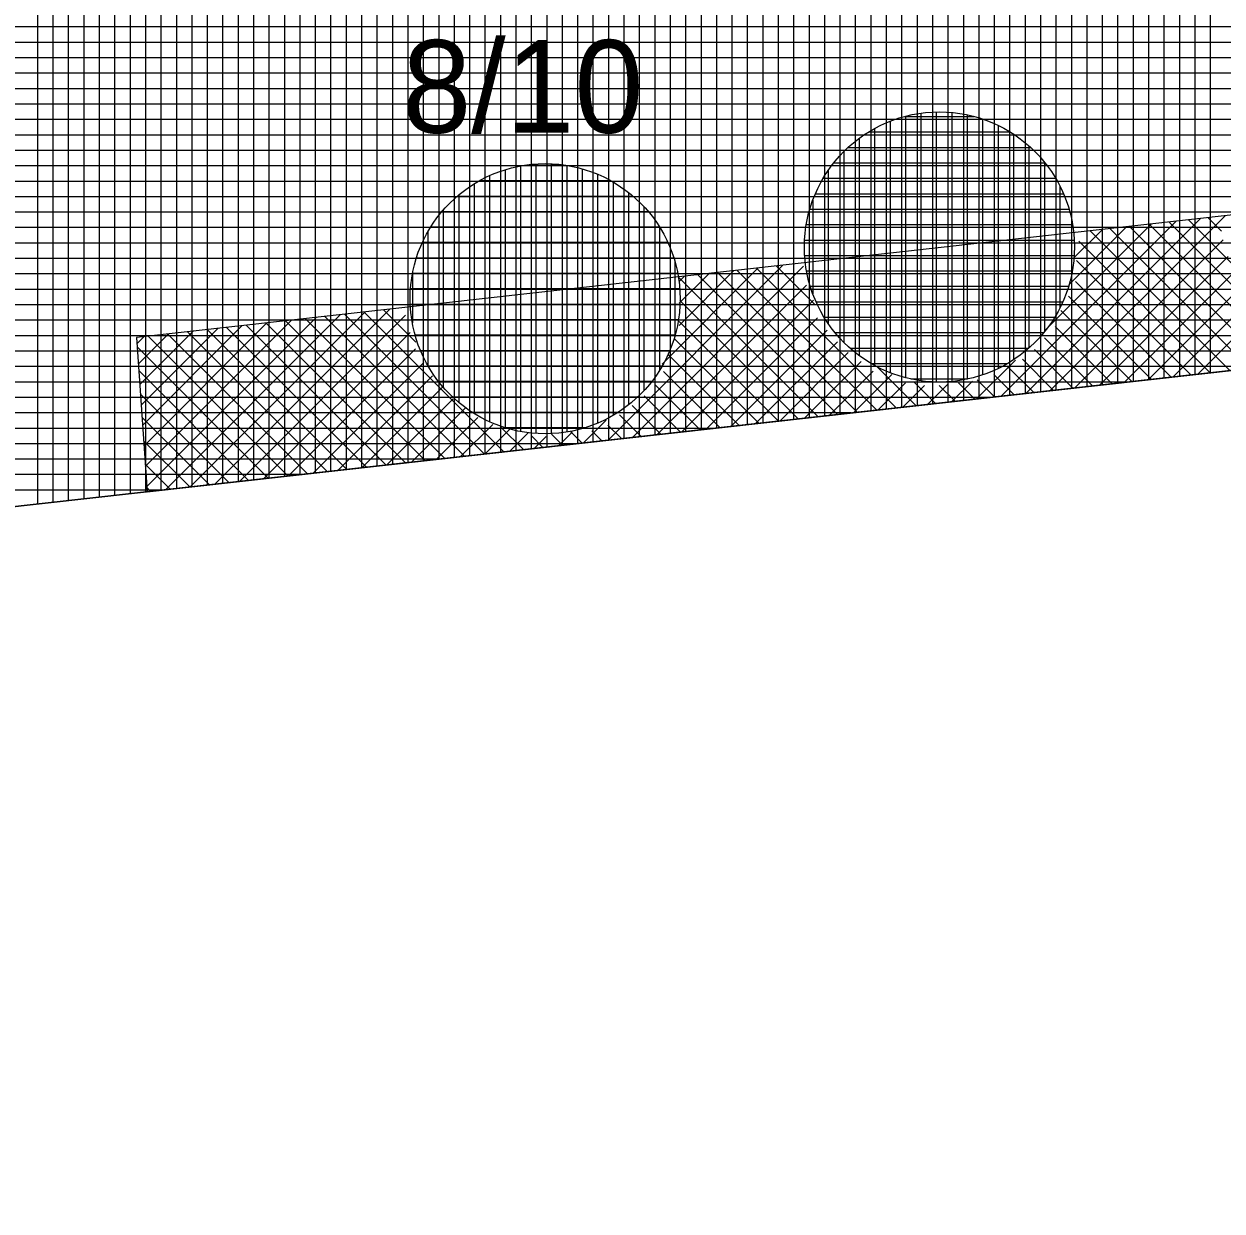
# Model space of a CAD drawing. Extents: x -565346 to -564154, y -1097386 to -1095620.
# Drawn here: x -565167.9 to -565152.37, y -1095873.28 to -1095857.9 of the extents above; entities that cross this region are included whole.
import ezdxf

# ---------------------------------------------------------------- set-up
doc = ezdxf.new("R2010")
doc.units = 0
for name, color, linetype in [('Vrstva 1', 7, 'Continuous'), ('Vrstva 40', 7, 'Continuous'), ('Vrstva 41', 7, 'Continuous'), ('Vrstva 42', 7, 'Continuous'), ('Vrstva 43', 7, 'Continuous'), ('Vrstva 44', 7, 'Continuous')]:
    doc.layers.add(name, color=color, linetype=linetype)

msp = doc.modelspace()

# ---------------------------------------------------------------- linework, layer by layer
at = {"layer": 'Vrstva 1'}
msp.add_line((-565052.84, -1095851.27), (-565230.93, -1095871.19), dxfattribs=at)
at = {"layer": 'Vrstva 41'}
for p, q in [((-565152.963, -1095860.456), (-565155.23, -1095862.723)), ((-565152.645, -1095860.42), (-565154.911, -1095862.687)), ((-565152.326, -1095860.385), (-565154.593, -1095862.651)), ((-565152.201, -1095861.041), (-565152.803, -1095860.438)), ((-565152.374, -1095860.584), (-565152.549, -1095860.41)), ((-565153.281, -1095860.492), (-565154.655, -1095861.865)), ((-565153.6, -1095860.527), (-565154.351, -1095861.279)), ((-565153.918, -1095860.563), (-565154.293, -1095860.937)), ((-565152.264, -1095862.391), (-565154.075, -1095860.58)), ((-565152.01, -1095862.363), (-565153.821, -1095860.552)), ((-565151.756, -1095862.334), (-565153.566, -1095860.523)), ((-565151.501, -1095862.306), (-565153.312, -1095860.495)), ((-565151.247, -1095862.277), (-565153.057, -1095860.466)), ((-565152.354, -1095860.696), (-565154.274, -1095862.616)), ((-565152.519, -1095862.419), (-565154.224, -1095860.714)), ((-565152.288, -1095860.912), (-565153.956, -1095862.58)), ((-565158.058, -1095861.026), (-565160.325, -1095863.293)), ((-565157.79, -1095861.04), (-565160.007, -1095863.257)), ((-565158.377, -1095861.061), (-565159.623, -1095862.307)), ((-565156.589, -1095862.875), (-565158.4, -1095861.064)), ((-565157.645, -1095861.535), (-565158.145, -1095861.036)), ((-565152.773, -1095862.448), (-565154.255, -1095860.965)), ((-565157.606, -1095862.988), (-565159.417, -1095861.178)), ((-565158.695, -1095861.097), (-565159.404, -1095861.806)), ((-565159.014, -1095861.133), (-565159.401, -1095861.519)), ((-565159.332, -1095861.168), (-565159.397, -1095861.233)), ((-565157.352, -1095862.96), (-565159.163, -1095861.149)), ((-565157.098, -1095862.932), (-565158.908, -1095861.121)), ((-565156.843, -1095862.903), (-565158.654, -1095861.092)), ((-565152.196, -1095861.104), (-565153.637, -1095862.545)), ((-565157.753, -1095861.287), (-565159.688, -1095863.221)), ((-565153.027, -1095862.476), (-565154.267, -1095861.237)), ((-565152.105, -1095861.295), (-565153.319, -1095862.509)), ((-565157.861, -1095863.017), (-565159.394, -1095861.484)), ((-565157.662, -1095861.478), (-565159.37, -1095863.186)), ((-565153.282, -1095862.505), (-565154.358, -1095861.428)), ((-565151.954, -1095861.426), (-565153.001, -1095862.473)), ((-565163.791, -1095861.667), (-565166.058, -1095863.934)), ((-565163.472, -1095861.631), (-565165.739, -1095863.898)), ((-565163.154, -1095861.596), (-565165.421, -1095863.863)), ((-565162.948, -1095861.672), (-565165.102, -1095863.827)), ((-565162.185, -1095863.501), (-565163.996, -1095861.69)), ((-565161.931, -1095863.472), (-565163.742, -1095861.662)), ((-565161.677, -1095863.444), (-565163.487, -1095861.633)), ((-565162.814, -1095862.024), (-565163.233, -1095861.605)), ((-565153.536, -1095862.533), (-565154.455, -1095861.615)), ((-565151.817, -1095861.573), (-565152.682, -1095862.438)), ((-565165.383, -1095861.845), (-565166.377, -1095862.839)), ((-565165.065, -1095861.809), (-565166.359, -1095863.104)), ((-565164.746, -1095861.774), (-565166.341, -1095863.369)), ((-565164.428, -1095861.738), (-565166.323, -1095863.633)), ((-565164.109, -1095861.703), (-565166.305, -1095863.898)), ((-565163.457, -1095863.643), (-565165.268, -1095861.832)), ((-565163.203, -1095863.614), (-565165.014, -1095861.804)), ((-565162.949, -1095863.586), (-565164.759, -1095861.775)), ((-565162.694, -1095863.558), (-565164.505, -1095861.747)), ((-565162.44, -1095863.529), (-565164.251, -1095861.718)), ((-565158.115, -1095863.045), (-565159.405, -1095861.755)), ((-565157.611, -1095861.709), (-565159.051, -1095863.15)), ((-565153.791, -1095862.562), (-565154.531, -1095861.821)), ((-565166.338, -1095861.952), (-565166.431, -1095862.045)), ((-565166.02, -1095861.916), (-565166.413, -1095862.31)), ((-565165.702, -1095861.881), (-565166.395, -1095862.574)), ((-565164.475, -1095863.757), (-565166.286, -1095861.946)), ((-565164.221, -1095863.728), (-565166.031, -1095861.918)), ((-565163.966, -1095863.7), (-565165.777, -1095861.889)), ((-565163.712, -1095863.671), (-565165.522, -1095861.861)), ((-565162.891, -1095861.899), (-565164.784, -1095863.791)), ((-565158.37, -1095863.074), (-565159.462, -1095861.982)), ((-565157.484, -1095861.866), (-565158.733, -1095863.114)), ((-565154.045, -1095862.59), (-565154.668, -1095861.968)), ((-565164.729, -1095863.785), (-565166.429, -1095862.086)), ((-565162.82, -1095862.11), (-565164.465, -1095863.756)), ((-565157.353, -1095862.017), (-565158.414, -1095863.079)), ((-565157.211, -1095862.159), (-565158.096, -1095863.043)), ((-565154.299, -1095862.619), (-565154.799, -1095862.119)), ((-565162.713, -1095862.287), (-565164.147, -1095863.72)), ((-565158.624, -1095863.102), (-565159.548, -1095862.178)), ((-565157.045, -1095862.275), (-565157.777, -1095863.008)), ((-565155.045, -1095862.255), (-565155.548, -1095862.758)), ((-565154.554, -1095862.647), (-565154.955, -1095862.245)), ((-565164.984, -1095863.814), (-565166.408, -1095862.39)), ((-565162.602, -1095862.458), (-565163.828, -1095863.684)), ((-565158.878, -1095863.131), (-565159.605, -1095862.405)), ((-565156.889, -1095862.401), (-565157.459, -1095862.972)), ((-565156.647, -1095862.443), (-565157.141, -1095862.936)), ((-565156.334, -1095862.846), (-565156.845, -1095862.335)), ((-565155.063, -1095862.704), (-565155.323, -1095862.443)), ((-565154.808, -1095862.676), (-565155.147, -1095862.337)), ((-565162.466, -1095862.604), (-565163.51, -1095863.649)), ((-565159.133, -1095863.159), (-565159.711, -1095862.581)), ((-565156.471, -1095862.549), (-565156.822, -1095862.901)), ((-565156.224, -1095862.586), (-565156.504, -1095862.865)), ((-565156.08, -1095862.818), (-565156.354, -1095862.544)), ((-565155.923, -1095862.567), (-565156.185, -1095862.83)), ((-565155.826, -1095862.789), (-565156.033, -1095862.583)), ((-565155.601, -1095862.529), (-565155.867, -1095862.794)), ((-565155.571, -1095862.761), (-565155.781, -1095862.551)), ((-565155.317, -1095862.732), (-565155.54, -1095862.51)), ((-565165.238, -1095863.842), (-565166.387, -1095862.693)), ((-565162.334, -1095862.756), (-565163.191, -1095863.613)), ((-565159.387, -1095863.188), (-565159.857, -1095862.717)), ((-565162.168, -1095862.872), (-565162.873, -1095863.578)), ((-565159.642, -1095863.216), (-565160.014, -1095862.844)), ((-565165.492, -1095863.871), (-565166.366, -1095862.997)), ((-565162.011, -1095862.999), (-565162.554, -1095863.542)), ((-565161.82, -1095863.09), (-565162.236, -1095863.506)), ((-565160.348, -1095863.032), (-565160.644, -1095863.328)), ((-565160.15, -1095863.273), (-565160.327, -1095863.097)), ((-565159.896, -1095863.245), (-565160.175, -1095862.965)), ((-565161.593, -1095863.147), (-565161.918, -1095863.471)), ((-565161.422, -1095863.415), (-565161.709, -1095863.129)), ((-565161.362, -1095863.198), (-565161.599, -1095863.435)), ((-565161.168, -1095863.387), (-565161.322, -1095863.232)), ((-565161.126, -1095863.244), (-565161.281, -1095863.399)), ((-565160.913, -1095863.358), (-565161.056, -1095863.216)), ((-565160.789, -1095863.191), (-565160.962, -1095863.364)), ((-565160.659, -1095863.33), (-565160.805, -1095863.185)), ((-565160.405, -1095863.301), (-565160.533, -1095863.173)), ((-565165.747, -1095863.899), (-565166.346, -1095863.3)), ((-565166.001, -1095863.927), (-565166.325, -1095863.604)), ((-565166.256, -1095863.956), (-565166.304, -1095863.908))]:
    msp.add_line(p, q, dxfattribs=at)
at = {"layer": 'Vrstva 42'}
msp.add_lwpolyline([(-565166.437, -1095861.963), (-565166.3, -1095863.961), (-565065.713, -1095852.71), (-565065.975, -1095850.726)], close=True, dxfattribs=at)
at = {"layer": 'Vrstva 43'}
for p, q in [((-565154.72, -1095848.037), (-565154.72, -1095862.666)), ((-565154.52, -1095848.023), (-565154.52, -1095862.643)), ((-565154.32, -1095848.009), (-565154.32, -1095862.621)), ((-565154.12, -1095847.996), (-565154.12, -1095862.599)), ((-565153.92, -1095847.982), (-565153.92, -1095862.576)), ((-565153.72, -1095847.968), (-565153.72, -1095862.554)), ((-565153.52, -1095847.954), (-565153.52, -1095862.531)), ((-565153.32, -1095847.941), (-565153.32, -1095862.509)), ((-565153.12, -1095847.927), (-565153.12, -1095862.487)), ((-565152.92, -1095847.913), (-565152.92, -1095862.464)), ((-565152.72, -1095847.9), (-565152.72, -1095862.442)), ((-565152.52, -1095847.886), (-565152.52, -1095862.42)), ((-565156.92, -1095848.188), (-565156.92, -1095862.912)), ((-565156.72, -1095848.174), (-565156.72, -1095862.889)), ((-565156.52, -1095848.16), (-565156.52, -1095862.867)), ((-565156.32, -1095848.146), (-565156.32, -1095862.845)), ((-565156.12, -1095848.133), (-565156.12, -1095862.822)), ((-565155.92, -1095848.119), (-565155.92, -1095862.8)), ((-565155.72, -1095848.105), (-565155.72, -1095862.777)), ((-565155.52, -1095848.092), (-565155.52, -1095862.755)), ((-565155.32, -1095848.078), (-565155.32, -1095862.733)), ((-565155.12, -1095848.064), (-565155.12, -1095862.71)), ((-565154.92, -1095848.05), (-565154.92, -1095862.688)), ((-565159.12, -1095848.339), (-565159.12, -1095863.158)), ((-565158.92, -1095848.325), (-565158.92, -1095863.135)), ((-565158.72, -1095848.311), (-565158.72, -1095863.113)), ((-565158.52, -1095848.297), (-565158.52, -1095863.091)), ((-565158.32, -1095848.284), (-565158.32, -1095863.068)), ((-565158.12, -1095848.27), (-565158.12, -1095863.046)), ((-565157.92, -1095848.256), (-565157.92, -1095863.024)), ((-565157.72, -1095848.243), (-565157.72, -1095863.001)), ((-565157.52, -1095848.229), (-565157.52, -1095862.979)), ((-565157.32, -1095848.215), (-565157.32, -1095862.956)), ((-565157.12, -1095848.201), (-565157.12, -1095862.934)), ((-565161.32, -1095848.489), (-565161.32, -1095863.404)), ((-565161.12, -1095848.476), (-565161.12, -1095863.382)), ((-565160.92, -1095848.462), (-565160.92, -1095863.359)), ((-565160.72, -1095848.448), (-565160.72, -1095863.337)), ((-565160.52, -1095848.435), (-565160.52, -1095863.314)), ((-565160.32, -1095848.421), (-565160.32, -1095863.292)), ((-565160.12, -1095848.407), (-565160.12, -1095863.27)), ((-565159.92, -1095848.393), (-565159.92, -1095863.247)), ((-565159.72, -1095848.38), (-565159.72, -1095863.225)), ((-565159.52, -1095848.366), (-565159.52, -1095863.203)), ((-565159.32, -1095848.352), (-565159.32, -1095863.18)), ((-565163.72, -1095848.654), (-565163.72, -1095863.672)), ((-565163.52, -1095848.64), (-565163.52, -1095863.65)), ((-565163.32, -1095848.627), (-565163.32, -1095863.628)), ((-565163.12, -1095848.613), (-565163.12, -1095863.605)), ((-565162.92, -1095848.599), (-565162.92, -1095863.583)), ((-565162.72, -1095848.585), (-565162.72, -1095863.56)), ((-565162.52, -1095848.572), (-565162.52, -1095863.538)), ((-565162.32, -1095848.558), (-565162.32, -1095863.516)), ((-565162.12, -1095848.544), (-565162.12, -1095863.493)), ((-565161.92, -1095848.531), (-565161.92, -1095863.471)), ((-565161.72, -1095848.517), (-565161.72, -1095863.449)), ((-565161.52, -1095848.503), (-565161.52, -1095863.426)), ((-565165.92, -1095848.805), (-565165.92, -1095863.918)), ((-565165.72, -1095848.791), (-565165.72, -1095863.896)), ((-565165.52, -1095848.778), (-565165.52, -1095863.874)), ((-565165.32, -1095848.764), (-565165.32, -1095863.851)), ((-565165.12, -1095848.75), (-565165.12, -1095863.829)), ((-565164.92, -1095848.736), (-565164.92, -1095863.807)), ((-565164.72, -1095848.723), (-565164.72, -1095863.784)), ((-565164.52, -1095848.709), (-565164.52, -1095863.762)), ((-565164.32, -1095848.695), (-565164.32, -1095863.739)), ((-565164.12, -1095848.681), (-565164.12, -1095863.717)), ((-565163.92, -1095848.668), (-565163.92, -1095863.695)), ((-565167.72, -1095848.928), (-565167.72, -1095864.12)), ((-565167.52, -1095848.915), (-565167.52, -1095864.097)), ((-565167.32, -1095848.901), (-565167.32, -1095864.075)), ((-565167.12, -1095848.887), (-565167.12, -1095864.053)), ((-565166.92, -1095848.874), (-565166.92, -1095864.03)), ((-565166.72, -1095848.86), (-565166.72, -1095864.008)), ((-565166.52, -1095848.846), (-565166.52, -1095863.986)), ((-565166.32, -1095848.832), (-565166.32, -1095863.963)), ((-565166.12, -1095848.819), (-565166.12, -1095863.941)), ((-565112.472, -1095857.94), (-565307.466, -1095857.94)), ((-565114.26, -1095858.14), (-565322.58, -1095858.14)), ((-565116.048, -1095858.34), (-565322.576, -1095858.34)), ((-565117.836, -1095858.54), (-565322.572, -1095858.54)), ((-565119.624, -1095858.74), (-565322.568, -1095858.74)), ((-565121.412, -1095858.94), (-565322.564, -1095858.94)), ((-565123.2, -1095859.14), (-565322.56, -1095859.14)), ((-565124.988, -1095859.34), (-565322.556, -1095859.34)), ((-565126.776, -1095859.54), (-565322.552, -1095859.54)), ((-565128.564, -1095859.74), (-565322.548, -1095859.74)), ((-565130.352, -1095859.94), (-565322.544, -1095859.94)), ((-565132.14, -1095860.14), (-565322.541, -1095860.14)), ((-565133.928, -1095860.34), (-565322.537, -1095860.34)), ((-565135.716, -1095860.54), (-565322.533, -1095860.54)), ((-565137.504, -1095860.74), (-565322.529, -1095860.74)), ((-565139.292, -1095860.94), (-565322.525, -1095860.94)), ((-565141.08, -1095861.14), (-565322.521, -1095861.14)), ((-565142.868, -1095861.34), (-565322.517, -1095861.34)), ((-565144.656, -1095861.54), (-565322.513, -1095861.54)), ((-565146.445, -1095861.74), (-565322.509, -1095861.74)), ((-565148.233, -1095861.94), (-565322.505, -1095861.94)), ((-565150.021, -1095862.14), (-565322.501, -1095862.14)), ((-565151.809, -1095862.34), (-565322.497, -1095862.34)), ((-565153.597, -1095862.54), (-565322.493, -1095862.54)), ((-565155.385, -1095862.74), (-565322.489, -1095862.74)), ((-565157.173, -1095862.94), (-565322.485, -1095862.94)), ((-565158.961, -1095863.14), (-565322.481, -1095863.14)), ((-565160.749, -1095863.34), (-565322.477, -1095863.34)), ((-565162.537, -1095863.54), (-565322.473, -1095863.54)), ((-565164.325, -1095863.74), (-565322.469, -1095863.74)), ((-565166.113, -1095863.94), (-565322.465, -1095863.94))]:
    msp.add_line(p, q, dxfattribs=at)
msp.add_lwpolyline([(-565311.82, -1095858.04), (-565322.62, -1095856.13), (-565322.28, -1095873.28), (-565318.28, -1095873.19), (-565230.93, -1095871.19), (-565052.84, -1095851.27), (-565052.77, -1095836.13), (-565130.42, -1095846.37), (-565188.3, -1095850.34), (-565231.27, -1095856.19)], close=True, dxfattribs=at)
at = {"layer": 'Vrstva 44'}
for p, q in [((-565156.27, -1095859.058), (-565156.27, -1095862.522)), ((-565156.07, -1095859.042), (-565156.07, -1095862.539)), ((-565155.87, -1095859.049), (-565155.87, -1095862.531)), ((-565156.67, -1095859.162), (-565156.67, -1095862.418)), ((-565156.481, -1095859.1), (-565155.583, -1095859.1)), ((-565156.47, -1095859.098), (-565156.47, -1095862.483)), ((-565155.67, -1095859.078), (-565155.67, -1095862.501)), ((-565155.47, -1095859.134), (-565155.47, -1095862.446)), ((-565155.27, -1095859.216), (-565155.27, -1095862.366)), ((-565156.947, -1095859.3), (-565155.116, -1095859.3)), ((-565156.87, -1095859.257), (-565156.87, -1095862.324)), ((-565155.07, -1095859.327), (-565155.07, -1095862.251)), ((-565157.211, -1095859.5), (-565154.85, -1095859.5)), ((-565157.07, -1095859.384), (-565157.07, -1095862.195)), ((-565154.87, -1095859.482), (-565154.87, -1095862.099)), ((-565157.27, -1095859.558), (-565157.27, -1095862.023)), ((-565161.66, -1095859.791), (-565161.66, -1095863.13)), ((-565161.46, -1095859.74), (-565161.46, -1095863.179)), ((-565161.392, -1095859.73), (-565160.889, -1095859.73)), ((-565161.26, -1095859.715), (-565161.26, -1095863.204)), ((-565161.06, -1095859.714), (-565161.06, -1095863.207)), ((-565160.86, -1095859.735), (-565160.86, -1095863.187)), ((-565160.66, -1095859.779), (-565160.66, -1095863.142)), ((-565157.47, -1095859.798), (-565157.47, -1095861.783)), ((-565157.397, -1095859.7), (-565154.663, -1095859.7)), ((-565154.67, -1095859.69), (-565154.67, -1095861.888)), ((-565162.06, -1095859.972), (-565162.06, -1095862.947)), ((-565161.985, -1095859.93), (-565160.293, -1095859.93)), ((-565161.86, -1095859.867), (-565161.86, -1095863.053)), ((-565160.46, -1095859.848), (-565160.46, -1095863.07)), ((-565160.26, -1095859.95), (-565160.26, -1095862.971)), ((-565157.537, -1095859.9), (-565154.525, -1095859.9)), ((-565162.274, -1095860.13), (-565160.005, -1095860.13)), ((-565162.26, -1095860.118), (-565162.26, -1095862.803)), ((-565160.06, -1095860.085), (-565160.06, -1095862.835)), ((-565157.636, -1095860.1), (-565154.422, -1095860.1)), ((-565154.47, -1095860.001), (-565154.47, -1095861.58)), ((-565159.86, -1095860.27), (-565159.86, -1095862.652)), ((-565157.708, -1095860.3), (-565154.352, -1095860.3)), ((-565157.67, -1095860.182), (-565157.67, -1095861.396)), ((-565162.474, -1095860.33), (-565159.804, -1095860.33)), ((-565162.46, -1095860.312), (-565162.46, -1095862.608)), ((-565162.66, -1095860.595), (-565162.66, -1095862.327)), ((-565162.62, -1095860.53), (-565159.66, -1095860.53)), ((-565159.66, -1095860.53), (-565159.66, -1095862.392)), ((-565157.755, -1095860.5), (-565154.306, -1095860.5)), ((-565162.73, -1095860.73), (-565159.551, -1095860.73)), ((-565157.777, -1095860.7), (-565154.284, -1095860.7)), ((-565157.775, -1095860.9), (-565154.284, -1095860.9)), ((-565162.806, -1095860.93), (-565159.473, -1095860.93)), ((-565159.46, -1095860.977), (-565159.46, -1095861.945)), ((-565162.86, -1095861.147), (-565162.86, -1095861.772)), ((-565162.857, -1095861.13), (-565159.423, -1095861.13)), ((-565157.75, -1095861.1), (-565154.309, -1095861.1)), ((-565162.884, -1095861.33), (-565159.397, -1095861.33)), ((-565157.702, -1095861.3), (-565154.358, -1095861.3)), ((-565162.889, -1095861.53), (-565159.393, -1095861.53)), ((-565157.629, -1095861.5), (-565154.432, -1095861.5)), ((-565157.523, -1095861.7), (-565154.535, -1095861.7)), ((-565162.868, -1095861.73), (-565159.412, -1095861.73)), ((-565162.824, -1095861.93), (-565159.455, -1095861.93)), ((-565157.381, -1095861.9), (-565154.68, -1095861.9)), ((-565162.755, -1095862.13), (-565159.525, -1095862.13)), ((-565157.187, -1095862.1), (-565154.871, -1095862.1)), ((-565156.911, -1095862.3), (-565155.148, -1095862.3)), ((-565162.658, -1095862.33), (-565159.623, -1095862.33)), ((-565162.522, -1095862.53), (-565159.757, -1095862.53)), ((-565156.4, -1095862.5), (-565155.667, -1095862.5)), ((-565162.343, -1095862.73), (-565159.938, -1095862.73)), ((-565162.089, -1095862.93), (-565160.193, -1095862.93)), ((-565161.66, -1095863.13), (-565160.624, -1095863.13))]:
    msp.add_line(p, q, dxfattribs=at)
for centre in [(-565156.03, -1095860.79), (-565161.14, -1095861.46)]:
    msp.add_circle(centre, 1.75, dxfattribs=at)

# ---------------------------------------------------------------- texts
at = {"layer": 'Vrstva 40'}
msp.add_text('8/10', height=1.2, dxfattribs=at).set_placement((-565162.99, -1095859.31))

doc.saveas('drawing.dxf')
